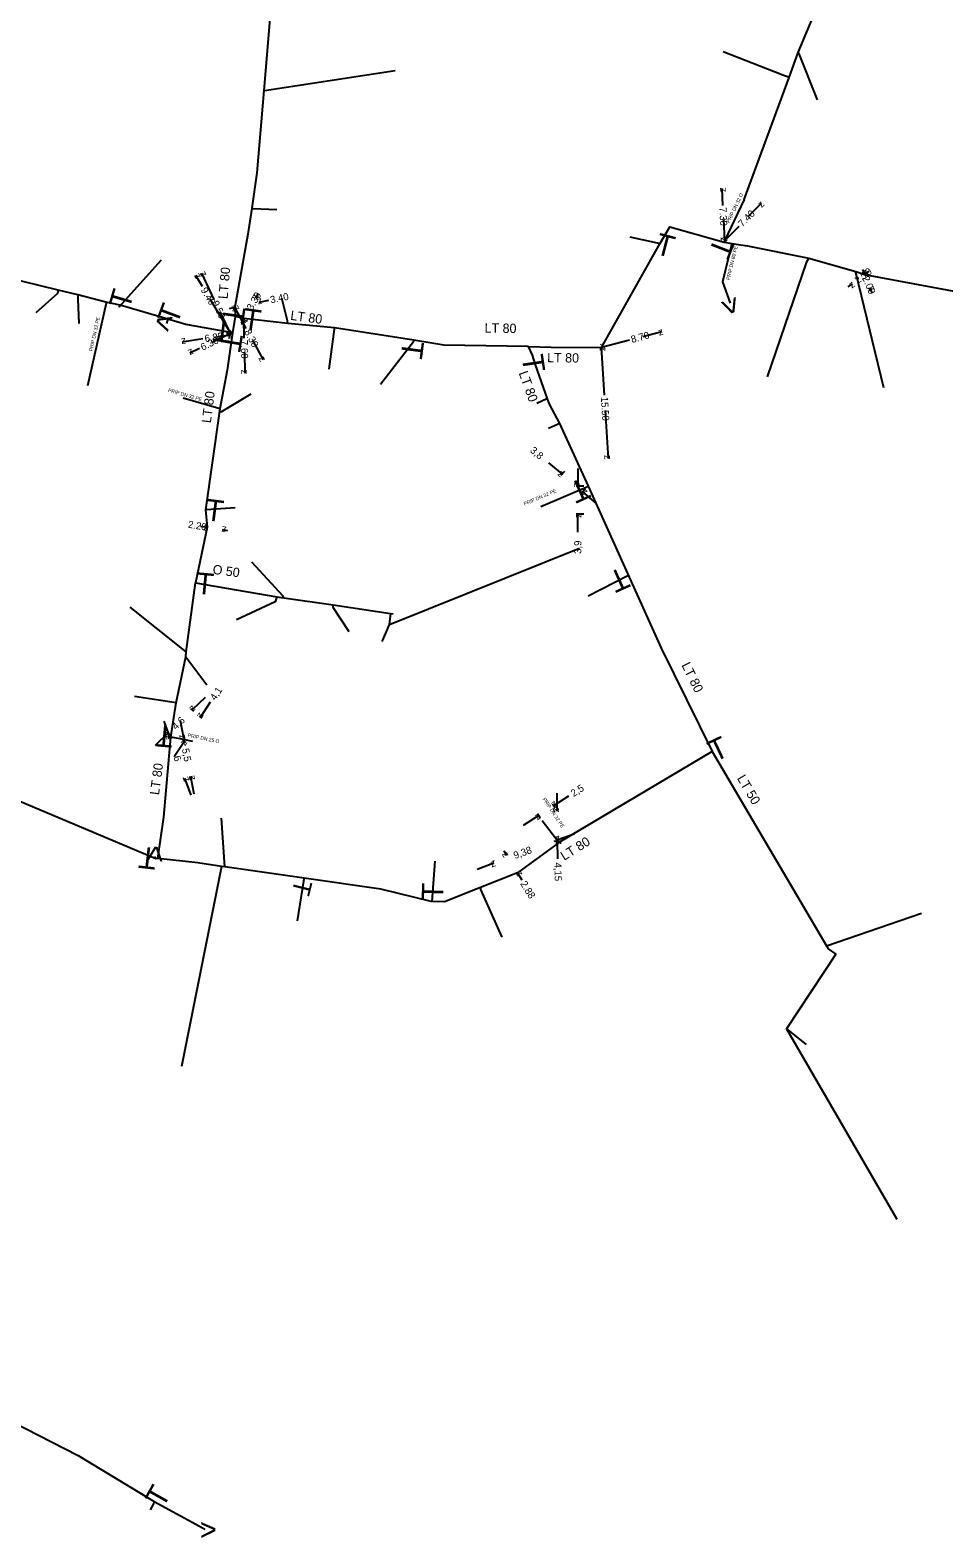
# Model space of a CAD drawing. Extents: x -634006 to -632185, y -1101085 to -1098649.
# Drawn here: x -632999.7 to -632872.2, y -1099354.1 to -1099143.7 of the extents above; entities that cross this region are included whole.
import ezdxf

# ---------------------------------------------------------------- set-up
doc = ezdxf.new("R2010")
doc.units = 0
for name, color, linetype in [('VP Hydrant', 7, 'Continuous'), ('VP Kótování', 7, 'Continuous'), ('VP Popis přípojky', 7, 'Continuous'), ('VP Přípojka', 7, 'Continuous'), ('VP Čára nerozlišená', 7, 'Continuous'), ('VP Řad', 7, 'Continuous'), ('VP Řad - popis', 7, 'Continuous'), ('VP Šoupě', 7, 'Continuous')]:
    doc.layers.add(name, color=color, linetype=linetype)

msp = doc.modelspace()

# ---------------------------------------------------------------- linework, layer by layer
at = {"layer": 'VP Kótování'}
for points in [[(-632903.05, -1099168.15), (-632903.16, -1099165.8)], [(-632902.91, -1099165.8), (-632902.91, -1099165.8)], [(-632899.46, -1099169.67), (-632897.64, -1099167.82)], [(-632897.39, -1099167.82), (-632897.39, -1099167.82)], [(-632902.97, -1099170.12), (-632902.83, -1099173.09)], [(-632900.84, -1099171.07), (-632902.83, -1099173.09)], [(-632902.58, -1099173.09), (-632902.58, -1099173.09)], [(-632902.58, -1099173.09), (-632902.58, -1099173.09)], [(-632883.56, -1099177.11), (-632883.27, -1099177.8)], [(-632882.67, -1099177.34), (-632883.27, -1099177.8)], [(-632975.66, -1099179.48), (-632976.59, -1099177.93)], [(-632976.34, -1099177.93), (-632976.34, -1099177.93)], [(-632974.04, -1099181.28), (-632975.78, -1099177.6)], [(-632975.53, -1099177.6), (-632975.53, -1099177.6)], [(-632885.54, -1099179.52), (-632884.94, -1099179.07)], [(-632884.64, -1099179.07), (-632884.64, -1099179.07)], [(-632883.57, -1099177.8), (-632883.57, -1099177.8)], [(-632882.97, -1099177.8), (-632882.97, -1099177.8)], [(-632882.2, -1099180.33), (-632882.49, -1099179.64)], [(-632882.19, -1099179.64), (-632882.19, -1099179.64)], [(-632974.65, -1099181.17), (-632971.76, -1099185.99)], [(-632967.89, -1099180.43), (-632968.26, -1099181.08)], [(-632968.01, -1099181.08), (-632968.01, -1099181.08)], [(-632966.47, -1099181.4), (-632967.83, -1099181.68)], [(-632967.58, -1099181.68), (-632967.58, -1099181.68)], [(-632973.2, -1099183.06), (-632971.72, -1099186.19)], [(-632971.89, -1099182.53), (-632971.16, -1099182.37)], [(-632971.41, -1099182.37), (-632971.41, -1099182.37)], [(-632969.57, -1099185.32), (-632971.16, -1099182.37)], [(-632970.91, -1099182.37), (-632970.91, -1099182.37)], [(-632970.25, -1099184.6), (-632969.89, -1099183.95)], [(-632969.84, -1099186.68), (-632969.89, -1099183.95)], [(-632969.64, -1099183.95), (-632969.64, -1099183.95)], [(-632969.64, -1099183.95), (-632969.64, -1099183.95)], [(-632914.2, -1099186.43), (-632911.58, -1099185.73)], [(-632975.62, -1099186.78), (-632978.49, -1099187.22)], [(-632978.24, -1099187.22), (-632978.24, -1099187.22)], [(-632974.3, -1099187.24), (-632971.76, -1099185.99)], [(-632973.69, -1099186.49), (-632971.72, -1099186.19)], [(-632972.01, -1099185.99), (-632972.01, -1099185.99)], [(-632972.01, -1099185.99), (-632972.01, -1099185.99)], [(-632971.97, -1099186.19), (-632971.97, -1099186.19)], [(-632971.47, -1099186.19), (-632971.47, -1099186.19)], [(-632968.63, -1099187.06), (-632967.22, -1099189.68)], [(-632916.1, -1099186.94), (-632919.98, -1099187.99)], [(-632919.59, -1099194.62), (-632919.98, -1099187.99)], [(-632976.09, -1099188.11), (-632977.42, -1099188.76)], [(-632977.17, -1099188.76), (-632977.17, -1099188.76)], [(-632969.81, -1099188.68), (-632969.76, -1099191.55)], [(-632966.97, -1099189.68), (-632966.97, -1099189.68)], [(-632969.51, -1099191.55), (-632969.51, -1099191.55)], [(-632919.47, -1099196.75), (-632919.07, -1099203.46)], [(-632927.4, -1099204.06), (-632925.49, -1099205.67)], [(-632923.28, -1099204.84), (-632923.29, -1099207.34)], [(-632925.15, -1099205.27), (-632925.65, -1099205.86)], [(-632922.43, -1099207.34), (-632923.54, -1099207.34)], [(-632922.25, -1099207.72), (-632922.75, -1099208.31)], [(-632920.67, -1099209.73), (-632922.59, -1099208.12)], [(-632975.97, -1099212.9), (-632975.03, -1099213.06)], [(-632922.43, -1099211.24), (-632923.54, -1099211.24)], [(-632923.29, -1099213.74), (-632923.29, -1099211.24)], [(-632972.12, -1099213.54), (-632972.86, -1099213.42)], [(-632976.9, -1099238.79), (-632977.29, -1099238.38)], [(-632975.31, -1099236.83), (-632977.12, -1099238.56)], [(-632974.58, -1099237.46), (-632975.97, -1099239.54)], [(-632981.09, -1099240.12), (-632980.22, -1099242.46)], [(-632978.81, -1099240.01), (-632978.34, -1099242.46)], [(-632976.13, -1099239.43), (-632975.76, -1099239.68)], [(-632982.25, -1099243.47), (-632980.44, -1099241.74)], [(-632980.22, -1099241.97), (-632980.61, -1099241.56)], [(-632980.34, -1099242.51), (-632980.46, -1099242.55)], [(-632978.34, -1099242.46), (-632978.09, -1099242.42)], [(-632979.63, -1099245.03), (-632978.25, -1099242.95)], [(-632978.41, -1099242.84), (-632978.04, -1099243.09)], [(-632978.26, -1099248.13), (-632978.38, -1099248.18)], [(-632977.27, -1099250.43), (-632978.14, -1099248.09)], [(-632977.3, -1099247.87), (-632977.05, -1099247.82)], [(-632976.83, -1099250.32), (-632977.3, -1099247.87)], [(-632924.57, -1099250.57), (-632926.67, -1099251.93)], [(-632926.24, -1099250.19), (-632926.2, -1099252.69)], [(-632930.88, -1099254.63), (-632928.77, -1099253.28)], [(-632928.55, -1099253.62), (-632928.91, -1099253.07)], [(-632926.45, -1099252.27), (-632926.81, -1099251.72)], [(-632926.68, -1099252.7), (-632926.45, -1099252.69)], [(-632926.6, -1099256.85), (-632926.37, -1099256.84)], [(-632926.29, -1099256.36), (-632926.25, -1099256.48)], [(-632923.82, -1099255.87), (-632926.17, -1099256.71)], [(-632926.08, -1099259.34), (-632926.12, -1099256.84)], [(-632935.12, -1099259.55), (-632935.08, -1099259.66)], [(-632933.63, -1099258.22), (-632933.23, -1099258.86)], [(-632937.34, -1099260.75), (-632934.99, -1099259.9)], [(-632931.08, -1099262.32), (-632931.71, -1099261.3)]]:
    msp.add_lwpolyline(points, dxfattribs=at)
at = {"layer": 'VP Přípojka'}
msp.add_line((-632979.33, -1099237.55), (-632985.15, -1099236.67), dxfattribs=at)
for points in [[(-632900.09, -1099167.33), (-632893.81, -1099150.32), (-632892.53, -1099146.83), (-632887.16, -1099133.92), (-632886.88, -1099133.28)], [(-632893.81, -1099150.32), (-632894.69, -1099149.98), (-632902.99, -1099146.74)], [(-632892.53, -1099146.83), (-632892.45, -1099147.01), (-632889.91, -1099153.43)], [(-632967.12, -1099152.13), (-632967.03, -1099152.11), (-632948.8, -1099149.32)], [(-632968.8, -1099168.54), (-632968.65, -1099168.58), (-632965.29, -1099168.73)], [(-632900.09, -1099167.33), (-632902.83, -1099173.09), (-632902.88, -1099173.3)], [(-632911.83, -1099173.52), (-632912.17, -1099173.44), (-632915.97, -1099172.57)], [(-632901.81, -1099173.47), (-632903.08, -1099178.81), (-632902.04, -1099181.79)], [(-632987.15, -1099182.09), (-632987.31, -1099182.28), (-632981.4, -1099175.75)], [(-632891.06, -1099175.5), (-632891.36, -1099176.02), (-632896.89, -1099192.05)], [(-632884.52, -1099177.36), (-632884.56, -1099177.47), (-632880.63, -1099193.56)], [(-632995.8, -1099179.97), (-632995.93, -1099180.45), (-632998.92, -1099183.14)], [(-632993.07, -1099180.63), (-632993.09, -1099181.24), (-632992.93, -1099184.65)], [(-632989.16, -1099181.63), (-632989.13, -1099181.79), (-632991.74, -1099193.34)], [(-632963.76, -1099184.61), (-632963.82, -1099184.25), (-632964.59, -1099181.07)], [(-632980.5, -1099184.03), (-632980.6, -1099184.3), (-632980.71, -1099184.65)], [(-632957.25, -1099185.23), (-632957.28, -1099185.44), (-632958.04, -1099190.99)], [(-632946.18, -1099186.97), (-632946.24, -1099187.17), (-632950.84, -1099193.15)], [(-632973.25, -1099196.52), (-632973.37, -1099196.48), (-632978.39, -1099195.03)], [(-632973.3, -1099196.88), (-632973.07, -1099196.94), (-632968.86, -1099194.45)], [(-632927.56, -1099195.13), (-632927.61, -1099195.14), (-632928.99, -1099195.79)], [(-632925.86, -1099198.59), (-632926.11, -1099198.71), (-632927.38, -1099199.29)], [(-632921.82, -1099207.38), (-632928.46, -1099210.19)], [(-632975.26, -1099210.63), (-632975.09, -1099210.57), (-632971.09, -1099210.29)], [(-632949.64, -1099226.64), (-632949.36, -1099226.53), (-632923.04, -1099215.96)], [(-632964.33, -1099222.9), (-632964.43, -1099222.67), (-632968.79, -1099217.94)], [(-632916.23, -1099219.79), (-632921.87, -1099222.67)], [(-632965.32, -1099222.75), (-632965.53, -1099223.47), (-632970.94, -1099225.99)], [(-632977.93, -1099230.46), (-632985.75, -1099224.19)], [(-632957.44, -1099223.91), (-632957.48, -1099224.19), (-632955.23, -1099227.6)], [(-632949.45, -1099225.08), (-632949.64, -1099226.64), (-632950.14, -1099227.82), (-632950.64, -1099229)], [(-632978.01, -1099231.15), (-632975.06, -1099235.03)], [(-632982.19, -1099259.35), (-633045.14, -1099232.8)], [(-632980.08, -1099242.33), (-632979.87, -1099242.33), (-632978.83, -1099242.56), (-632977.08, -1099242.92)], [(-632972.57, -1099260.44), (-632973, -1099253.64)], [(-632925.86, -1099257.02), (-632926.12, -1099256.83), (-632928.28, -1099254.04)], [(-632981.91, -1099259.29), (-632982.19, -1099259.35), (-632982.36, -1099259.03)], [(-632973, -1099260.39), (-632978.62, -1099288.33)], [(-632943.6, -1099265.28), (-632943.22, -1099259.64)], [(-632961.46, -1099262.03), (-632961.56, -1099262.45), (-632962.44, -1099267.96)], [(-632936.86, -1099263.32), (-632936.86, -1099263.59), (-632933.91, -1099270.26)], [(-632888.59, -1099271.46), (-632875.33, -1099266.91)], [(-632887.29, -1099272.63), (-632894.16, -1099283.05), (-632878.75, -1099309.6)], [(-632894.16, -1099283.05), (-632891.44, -1099285.24)], [(-632982.4, -1099349.02), (-632982.46, -1099349.23), (-632982.97, -1099350.16)], [(-632975.29, -1099352.9), (-632975.57, -1099352.71)]]:
    msp.add_lwpolyline(points, dxfattribs=at)
at = {"layer": 'VP Čára nerozlišená'}
msp.add_lwpolyline([(-632975.29, -1099352.9), (-632975.57, -1099352.71)], dxfattribs=at)
at = {"layer": 'VP Řad'}
for points in [[(-632959.7, -1099086.72), (-632962.23, -1099103.32), (-632964.06, -1099110.94), (-632964.07, -1099111.17), (-632964.78, -1099123.78), (-632965.25, -1099129.78), (-632967.12, -1099152.13), (-632968.08, -1099163.6), (-632968.8, -1099168.54), (-632969.33, -1099172.17), (-632971.16, -1099182.37), (-632971.11, -1099183.63)], [(-633044.21, -1099168.63), (-633044.29, -1099168.91), (-633048.42, -1099181.84), (-633048.92, -1099183.41), (-633052.64, -1099199.53), (-633053.2, -1099204.37), (-633055.71, -1099212.08), (-633072.65, -1099283.12), (-633073.76, -1099288.7), (-633076.34, -1099298.14), (-633073.12, -1099300.19), (-633061.55, -1099306.56), (-633044.1, -1099315.91), (-633040.61, -1099318.45), (-633032.14, -1099321.95), (-633022.9, -1099327.34), (-633020.04, -1099328.47), (-633014.32, -1099331.98), (-633002.17, -1099337.9), (-632993.01, -1099342.57), (-632982.4, -1099349.02), (-632975.57, -1099352.71)], [(-632971.47, -1099185.91), (-632977.98, -1099184.77), (-632980.5, -1099184.03), (-632987.15, -1099182.09), (-632989.16, -1099181.63), (-632993.07, -1099180.63), (-632995.8, -1099179.97), (-633008.17, -1099176.97), (-633010.43, -1099176.42), (-633023.34, -1099173.28), (-633024.93, -1099172.99), (-633029.92, -1099172.11), (-633031.48, -1099171.72), (-633044.21, -1099168.63)], [(-632930.2, -1099187.82), (-632927.02, -1099187.92), (-632919.98, -1099187.99), (-632911.83, -1099173.52), (-632910.46, -1099171.15), (-632902.88, -1099173.3), (-632901.81, -1099173.47), (-632899.59, -1099173.81)], [(-632899.59, -1099173.81), (-632891.06, -1099175.5), (-632884.48, -1099177.38), (-632883.27, -1099177.8), (-632798.64, -1099193.56), (-632797.29, -1099193.81)], [(-632971.11, -1099183.63), (-632971.47, -1099185.91)], [(-632930.2, -1099187.82), (-632941.97, -1099187.64), (-632946.18, -1099186.97), (-632957.25, -1099185.23), (-632963.76, -1099184.61), (-632969.89, -1099183.95), (-632971.11, -1099183.63)], [(-632971.47, -1099185.91), (-632972.23, -1099191.15), (-632973.25, -1099196.52), (-632973.3, -1099196.88), (-632975.26, -1099210.63), (-632975.03, -1099213.06), (-632976.63, -1099220.81)], [(-632930.2, -1099187.82), (-632930.2, -1099187.82), (-632929.66, -1099189.06), (-632929.23, -1099190.41), (-632927.56, -1099195.13), (-632927.29, -1099195.87), (-632925.86, -1099198.59), (-632921.85, -1099207.31), (-632911.66, -1099229.93), (-632904.53, -1099244.36), (-632925.86, -1099257.02), (-632931.71, -1099261.3), (-632936.86, -1099263.32), (-632941.88, -1099265.32), (-632943.76, -1099265.28), (-632950.79, -1099263.56), (-632961.46, -1099262.03), (-632972.57, -1099260.44), (-632973, -1099260.39), (-632976.31, -1099259.9), (-632981.91, -1099259.29), (-632981.09, -1099253.51), (-632980.08, -1099242.33), (-632979.33, -1099237.55), (-632978.01, -1099231.15), (-632977.93, -1099230.46), (-632976.63, -1099220.81)], [(-632976.63, -1099220.81), (-632965.32, -1099222.75), (-632964.33, -1099222.9), (-632957.44, -1099223.91), (-632949.45, -1099225.08), (-632949.06, -1099225.14)], [(-632904.53, -1099244.36), (-632888.59, -1099271.46), (-632888.36, -1099271.88), (-632887.29, -1099272.63)]]:
    msp.add_lwpolyline(points, dxfattribs=at)

# ---------------------------------------------------------------- texts
at = {"layer": 'VP Hydrant'}
for rotation, p in [(289.2764, (-632903.7, -1099181.58)), (162.2077, (-632979.54, -1099183.45)), (83.4435, (-632980.96, -1099259.95)), (1.0615, (-632976.01, -1099354.42))]:
    msp.add_text('>', height=3, rotation=rotation, dxfattribs=at).set_placement(p)
at = {"layer": 'VP Kótování'}
for s, rotation, p in [('z', 92.5758, (-632902.64, -1099166.28)), ('7.30', 272.5758, (-632903.54, -1099168.42)), ('7.40', 45.4326, (-632900.31, -1099171.24)), ('z', 45.4326, (-632897.63, -1099168.53)), ('z', 272.5758, (-632903.35, -1099172.61)), ('z', 225.4326, (-632902.84, -1099172.38)), ('z', 115.3161, (-632975.11, -1099177.84)), ('2.10', 37.2627, (-632884.21, -1099179.14)), ('z', 292.7697, (-632883.92, -1099177.53)), ('z', 217.2626, (-632883.17, -1099177.1)), ('z', 120.9282, (-632975.9, -1099178.1)), ('9.40', 300.9282, (-632975.96, -1099179.95)), ('z', 37.2627, (-632885.04, -1099179.77)), ('2.00', 292.7697, (-632883.62, -1099178.25)), ('z', 112.7697, (-632881.84, -1099179.91)), ('9.50', 295.316, (-632974.39, -1099181.72)), ('3.30', 60.4814, (-632968.71, -1099182.88)), ('z', 240.4813, (-632968.45, -1099180.4)), ('z', 191.7662, (-632967.44, -1099181.09)), ('3.40', 11.7662, (-632966.12, -1099181.83)), ('z', 11.7662, (-632971.54, -1099182.96)), ('z', 118.3157, (-632970.48, -1099182.58)), ('z', 60.4814, (-632969.7, -1099184.63)), ('z', 90.9423, (-632969.38, -1099184.44)), ('6.85', 8.673, (-632975.3, -1099187.24)), ('z', 300.9282, (-632972.44, -1099185.82)), ('z', 295.316, (-632972.38, -1099185.95)), ('z', 26.0486, (-632971.99, -1099186.66)), ('z', 8.673, (-632972.14, -1099186.76)), ('8.30', 298.3157, (-632969.89, -1099185.78)), ('8.70', 15.0298, (-632915.73, -1099187.36)), ('z', 15.0298, (-632911.93, -1099186.34)), ('z', 188.673, (-632978.07, -1099186.65)), ('6.30', 26.0486, (-632975.65, -1099188.45)), ('7.60', 270.9423, (-632970.34, -1099186.94)), ('z', 93.373, (-632919.45, -1099188.46)), ('z', 195.0299, (-632919.63, -1099187.37)), ('z', 206.0486, (-632977.19, -1099188.09)), ('z', 298.3157, (-632967.9, -1099189.48)), ('z', 270.9423, (-632970.27, -1099191.06)), ('15.50', 273.3729, (-632920.08, -1099194.89)), ('3,8', 319.854, (-632930.04, -1099202.48)), ('z', 273.373, (-632919.6, -1099202.99)), ('z', 319.854, (-632926.19, -1099205.73)), ('z', 269.9304, (-632923.79, -1099206.84)), ('z', 139.854, (-632921.88, -1099208.06)), ('z', 89.9304, (-632922.79, -1099211.74)), ('2.20', 350.5291, (-632977.75, -1099213.11)), ('z', 350.5291, (-632975.61, -1099213.47)), ('z', 170.5291, (-632972.28, -1099213.01)), ('3,9', 89.9304, (-632922.8, -1099216.78)), ('4,1', 56.2457, (-632973.88, -1099237.32)), ('z', 223.7777, (-632977.1, -1099237.85)), ('4,6', 43.7777, (-632979.37, -1099241.4)), ('z', 236.2457, (-632976.11, -1099238.85)), ('z', 43.7777, (-632980.46, -1099242.45)), ('z', 290.2972, (-632980.86, -1099242.17)), ('z', 280.8795, (-632978.92, -1099242.07)), ('z', 56.2457, (-632978.11, -1099243.64)), ('5,5', 280.8795, (-632978.55, -1099244.01)), ('6', 290.2972, (-632979.76, -1099245.15)), ('z', 110.2972, (-632977.5, -1099248.39)), ('z', 100.8795, (-632976.71, -1099248.26)), ('2,5', 32.7995, (-632923.88, -1099250.72)), ('z', 32.7995, (-632928.92, -1099253.97)), ('z', 212.7995, (-632926.52, -1099251.23)), ('z', 271.0427, (-632926.71, -1099252.2)), ('z', 199.8434, (-632925.87, -1099256.07)), ('z', 91.0427, (-632925.61, -1099257.33)), ('z', 301.9021, (-632933.92, -1099258.7)), ('9,38', 19.8434, (-632932.06, -1099259.37)), ('z', 19.8434, (-632935.29, -1099260.54)), ('z', 121.902, (-632931.02, -1099261.47)), ('4,15', 271.0427, (-632926.57, -1099259.85)), ('2.88', 301.9021, (-632931.37, -1099262.8))]:
    msp.add_text(s, height=1, rotation=rotation, dxfattribs=at).set_placement(p)
at = {"layer": 'VP Popis přípojky'}
for s, rotation, p in [('PRIP DN 32 O', 64.5556, (-632902.13, -1099170.64)), ('PRIP DN 80 PE', 76.5587, (-632902.11, -1099178.6)), ('PRIP DN 32 PE', 77.2644, (-632991.04, -1099188.54)), ('PRIP DN 32 PE', 343.8631, (-632980.51, -1099194.14)), ('PRIP DN 32 PE', 22.9532, (-632930.72, -1099210.06)), ('PRIP DN 25 O', 348.326, (-632977.77, -1099242.3)), ('PRIP DN 32 PE', 303.3717, (-632928.24, -1099251))]:
    msp.add_text(s, height=0.5, rotation=rotation, dxfattribs=at).set_placement(p)
at = {"layer": 'VP Řad - popis'}
for s, rotation, p in [('LT 80', 85.217, (-632972.17, -1099181.25)), ('LT 80', 352.475, (-632963.46, -1099184.11)), ('LT 80', 359.0941, (-632936.31, -1099185.89)), ('LT 80', 359.0977, (-632927.58, -1099190.02)), ('LT 80', 289.883, (-632931.56, -1099191.53)), ('LT 80', 82.7093, (-632974.51, -1099198.58)), ('O 50', 352.2982, (-632974.31, -1099219.55)), ('LT 80', 296.2849, (-632908.86, -1099232.29)), ('LT 80', 82.33, (-632981.75, -1099250.48)), ('LT 50', 300.4553, (-632901.12, -1099248.08)), ('LT 80', 31.9442, (-632925.2, -1099259.62))]:
    msp.add_text(s, height=1.3, rotation=rotation, dxfattribs=at).set_placement(p)
at = {"layer": 'VP Šoupě'}
for height, rotation, p in [(3, 345.2815, (-632912.64, -1099174.87)), (3, 248.7028, (-632904.2, -1099172.46)), (3, 73.5811, (-632985.9, -1099182.79)), (3, 69.4675, (-632979.23, -1099184.91)), (3, 261.7559, (-632972.63, -1099182.06)), (3, 351.756, (-632970.19, -1099185.42)), (3, 172.5401, (-632971.45, -1099184.38)), (3, 260.8567, (-632972.98, -1099185.82)), (3, 262.4124, (-632947.71, -1099186.88)), (3, 278.3824, (-632931.15, -1099189.19)), (3, 204.2746, (-632922.55, -1099206.05)), (3, 352.7093, (-632975.37, -1099212.05)), (3, 354.801, (-632976.69, -1099222.32)), (3, 204.2746, (-632917.03, -1099218.52)), (3, 174.801, (-632979.64, -1099240.85)), (3, 25.4289, (-632904.18, -1099245.88)), (3, 173.4435, (-632981.93, -1099257.87)), (2.5, 255.9999, (-632962.75, -1099262.07)), (3, 88.6614, (-632942.09, -1099265.19)), (3, 60.4843, (-632981.2, -1099350.05))]:
    msp.add_text('T', height=height, rotation=rotation, dxfattribs=at).set_placement(p)

doc.saveas('drawing.dxf')
